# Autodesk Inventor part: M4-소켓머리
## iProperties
IsCustomPart: 0
Company: 한국ATC센터
Created: 2014-08
Part Number: M4-소켓머리
Material: 강, 연강
Description: 6각머리 태핑 나사
Document SubType Name: Modeling
Standard: KS B 1003
Designer: KYOUNG IL JANG
Standards Organization: KS
Language: ko-KR
Size Designation: M 4 x 12
Categories: <MemberInstance><Categories><Category DisplayName="조임쇠" InternalName="e4da775c-781d-43d5-af7c-5136215cf5a6" Mnemonic="FSTN"><Category DisplayName="볼트" InternalN
Density: 7.86 g/cm^3
Checked By: KYOUNG IL JANG
Mass: 2.23465 g
Surface Area: 3.30853 cm^2
Volume: 0.284306 cm^3
Author: KYOUNG IL JANG
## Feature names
1. Fillet2
